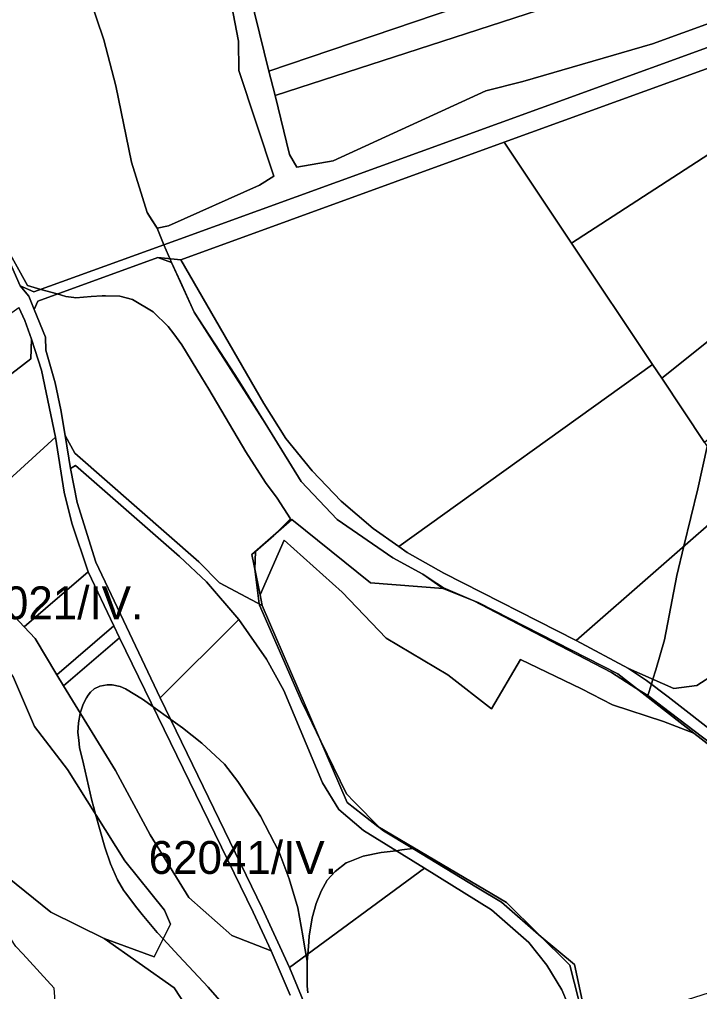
# Model space of a CAD drawing. Extents: x -521939 to -516426, y -1197857 to -1189551.
# Drawn here: x -518736 to -518425.7, y -1194982.1 to -1194538.7 of the extents above; entities that cross this region are included whole.
import ezdxf

# ---------------------------------------------------------------- set-up
doc = ezdxf.new("R2010")
doc.units = 0
for name, color, linetype in [('95560013', 7, 'Continuous'), ('95610013', 7, 'Continuous'), ('95620013', 7, 'Continuous'), ('95640013', 7, 'Continuous'), ('95660013', 7, 'Continuous')]:
    doc.layers.add(name, color=color, linetype=linetype)

msp = doc.modelspace()

# ---------------------------------------------------------------- linework, layer by layer
at = {"layer": '95560013'}
for points in [[(-518410.36, -1194442.61), (-518392.22, -1194484.25), (-518451.13, -1194504.23), (-518622.14, -1194562.23), (-518632.98, -1194518.19), (-518460.61, -1194459.67)], [(-518622.14, -1194562.23), (-518451.13, -1194504.23), (-518392.22, -1194484.25), (-518386.35, -1194497.79), (-518450.38, -1194518.57), (-518619.36, -1194573.41)], [(-518373.59, -1194527.14), (-518419.54, -1194539.87), (-518447.07, -1194549.8), (-518506.27, -1194566.99), (-518523.18, -1194571.3), (-518592.86, -1194603.17), (-518609.4, -1194606.14), (-518612.69, -1194600.31), (-518619.36, -1194573.41), (-518450.38, -1194518.57), (-518386.35, -1194497.79)], [(-518367.68, -1194539.54), (-518356.28, -1194557.82), (-518484.07, -1194640.7), (-518514.78, -1194594.72), (-518386.51, -1194548.14)], [(-518447.08, -1194696.09), (-518484.07, -1194640.7), (-518356.28, -1194557.82), (-518340.99, -1194583.11), (-518325.54, -1194608.45), (-518442.87, -1194702.39)], [(-518562.92, -1194779.16), (-518574.64, -1194770.93), (-518589.15, -1194758.48), (-518602.39, -1194744.68), (-518614.37, -1194729.87), (-518624.47, -1194713.9), (-518662.28, -1194648.3), (-518514.78, -1194594.72), (-518484.07, -1194640.7), (-518447.08, -1194696.09)], [(-518423.4, -1194731.62), (-518442.87, -1194702.39), (-518325.54, -1194608.45), (-518307.55, -1194638.13)], [(-518730.4, -1194684.49), (-518730.79, -1194693.56), (-518777.63, -1194729.6), (-518855.5, -1194789.32), (-518865.86, -1194763.22), (-518860.9, -1194759.36), (-518736.23, -1194670.16), (-518733.51, -1194676.1)], [(-518481.99, -1194821.99), (-518542.37, -1194791.36), (-518559, -1194781.92), (-518562.92, -1194779.16), (-518447.08, -1194696.09), (-518442.87, -1194702.39), (-518423.4, -1194731.62), (-518412.48, -1194747.98), (-518406.89, -1194756.35)], [(-518481.99, -1194821.99), (-518406.89, -1194756.35), (-518395.85, -1194772.88), (-518376.44, -1194801.94), (-518410.77, -1194832.23), (-518426.93, -1194842.54), (-518437.35, -1194843.87), (-518458.12, -1194834.75)]]:
    msp.add_lwpolyline(points, close=True, dxfattribs=at)
at = {"layer": '95610013'}
msp.add_lwpolyline([(-518648.33, -1194484.39), (-518635.96, -1194548.55), (-518635.85, -1194562), (-518619.89, -1194610.13), (-518626.4, -1194614.29), (-518667.97, -1194632.81), (-518673.12, -1194633.99), (-518677.75, -1194626.77), (-518684.82, -1194603.84), (-518691.92, -1194568.93), (-518697.48, -1194547.94), (-518710.33, -1194509.64)], dxfattribs=at)
for points in [[(-518667.07, -1194951.45), (-518674.42, -1194966.29), (-518697.27, -1194957.86), (-518721.6, -1194945.89), (-518745.52, -1194926.78), (-518800.02, -1194866.93), (-518820.29, -1194839.32), (-518835.53, -1194820.44), (-518765.72, -1194771.38), (-518719.57, -1194729.28), (-518715.58, -1194754.38), (-518712.02, -1194768.46), (-518704.64, -1194790.68), (-518733.74, -1194815.77), (-518749.9, -1194798.59), (-518761.09, -1194783.03), (-518767.51, -1194780.53), (-518770.85, -1194784.96), (-518750.08, -1194821.88), (-518738.64, -1194838.92), (-518729.05, -1194861.24), (-518713.96, -1194880.83), (-518687.89, -1194922.47), (-518669.78, -1194944.97)], [(-518635.94, -1194812.42), (-518671.75, -1194848.16), (-518701.05, -1194786.3), (-518709.67, -1194758.99), (-518712.72, -1194743.47), (-518710.37, -1194742.17), (-518662.98, -1194783.62), (-518650.66, -1194795.28)], [(-518692.91, -1194815.24), (-518718.88, -1194837.59), (-518728.73, -1194821.13), (-518733.74, -1194815.77), (-518704.64, -1194790.68)], [(-518551.19, -1194925.86), (-518612.73, -1194971.22), (-518625.28, -1194944.03), (-518671.75, -1194848.16), (-518635.94, -1194812.42), (-518623.29, -1194830.57), (-518615.31, -1194844.82), (-518597.64, -1194886.99), (-518590.23, -1194899.11), (-518578.98, -1194908.61)], [(-518690.24, -1194820.82), (-518715.84, -1194842.65), (-518718.88, -1194837.59), (-518692.91, -1194815.24)], [(-518690.24, -1194820.82), (-518629.33, -1194945.99), (-518621.14, -1194963.55), (-518639.03, -1194956.62), (-518658.6, -1194939.28), (-518676.38, -1194910.65), (-518692.19, -1194881.36), (-518715.84, -1194842.65)], [(-518612.73, -1194971.22), (-518551.19, -1194925.86), (-518520.66, -1194944.85), (-518503.52, -1194959.79), (-518495.28, -1194970.1), (-518488.5, -1194981.42), (-518483.3, -1194993.56), (-518479.79, -1195006.28), (-518583.67, -1195045.33), (-518599.24, -1195003.9)]]:
    msp.add_lwpolyline(points, close=True, dxfattribs=at)
at = {"layer": '95620013'}
for points in [[(-518442.17, -1194859), (-518465.35, -1194851.3), (-518479.49, -1194844.01), (-518507.34, -1194830.62), (-518520.62, -1194853.23), (-518540.54, -1194837.64), (-518568.59, -1194820.97), (-518588.67, -1194800), (-518615.19, -1194776.18), (-518626.13, -1194801.22), (-518629.87, -1194782.81), (-518611.71, -1194766.87), (-518575.86, -1194795.7), (-518542.69, -1194798.26), (-518526.37, -1194804.79), (-518463.01, -1194837.27), (-518428.24, -1194864.28)], [(-518477.04, -1195000.54), (-518484.79, -1194970.06), (-518513.79, -1194941.58), (-518572.38, -1194906.86), (-518586.43, -1194895.87), (-518625.17, -1194805.96), (-518626.13, -1194801.22), (-518615.19, -1194776.18), (-518588.67, -1194800), (-518568.59, -1194820.97), (-518540.54, -1194837.64), (-518520.62, -1194853.23), (-518507.34, -1194830.62), (-518479.49, -1194844.01), (-518465.35, -1194851.3), (-518442.17, -1194859), (-518428.24, -1194864.28), (-518400.82, -1194885.57), (-518302.06, -1194944.78)]]:
    msp.add_lwpolyline(points, close=True, dxfattribs=at)
at = {"layer": '95640013'}
for points in [[(-518719.92, -1194464.77), (-518710.33, -1194509.64), (-518697.48, -1194547.94), (-518691.92, -1194568.93), (-518684.82, -1194603.84), (-518677.75, -1194626.77), (-518673.12, -1194633.99), (-518670.02, -1194641.47), (-518729.32, -1194662.99), (-518735.68, -1194660.28), (-518749.75, -1194628.33), (-518778.85, -1194562.27), (-518784.67, -1194547.47), (-518789.28, -1194532.25), (-518792.66, -1194516.7), (-518794.77, -1194500.94), (-518795.17, -1194469.16), (-518789.82, -1194390.1), (-518787.62, -1194357.85), (-518785.49, -1194356.68), (-518774.24, -1194362.95), (-518768.4, -1194363.91), (-518713.15, -1194395.12), (-518719.42, -1194447.81)], [(-518625.17, -1194805.96), (-518644.64, -1194795.63), (-518654.08, -1194786.18), (-518710.66, -1194736.6), (-518715.14, -1194728.52), (-518717.06, -1194716.71), (-518719.62, -1194704.53), (-518723.86, -1194689.63), (-518724.12, -1194683.6), (-518729.2, -1194670.98), (-518727.55, -1194667.14), (-518672.89, -1194647.3), (-518666.51, -1194649.62), (-518656.27, -1194672.17), (-518623.89, -1194722.86), (-518607.41, -1194749.43), (-518591.06, -1194766.84), (-518565.58, -1194784.24), (-518551.9, -1194791.69), (-518542.69, -1194798.26), (-518575.86, -1194795.7), (-518611.71, -1194766.87), (-518629.87, -1194782.81), (-518626.13, -1194801.22)], [(-518719.57, -1194729.28), (-518765.72, -1194771.38), (-518766.88, -1194766.36), (-518770.01, -1194755.88), (-518773.9, -1194742.58), (-518777.63, -1194729.6), (-518730.79, -1194693.56), (-518730.4, -1194684.49), (-518725.91, -1194698.62)], [(-518458.12, -1194834.75), (-518437.35, -1194843.87), (-518426.93, -1194842.54), (-518410.77, -1194832.23), (-518376.44, -1194801.94), (-518335.14, -1194763.37), (-518297.28, -1194730.31), (-518275.98, -1194713.4), (-518265.96, -1194706.53), (-518259.19, -1194717.76), (-518284.47, -1194739.67), (-518413.12, -1194851.17), (-518415.72, -1194854.89), (-518417.07, -1194860.7), (-518416.02, -1194866.37), (-518440.03, -1194847.7), (-518449.87, -1194840.31)]]:
    msp.add_lwpolyline(points, close=True, dxfattribs=at)
for points in [[(-518398.68, -1194543), (-518498.27, -1194579.14), (-518664.63, -1194639.51), (-518670.02, -1194641.47), (-518673.12, -1194633.99), (-518667.97, -1194632.81), (-518626.4, -1194614.29), (-518619.89, -1194610.13), (-518635.85, -1194562), (-518635.96, -1194548.55), (-518648.33, -1194484.39), (-518643.9, -1194474.45), (-518632.98, -1194518.19), (-518622.14, -1194562.23), (-518619.36, -1194573.41), (-518612.69, -1194600.31), (-518609.4, -1194606.14), (-518592.86, -1194603.17), (-518523.18, -1194571.3), (-518506.27, -1194566.99), (-518447.07, -1194549.8), (-518419.54, -1194539.87)], [(-518386.51, -1194548.14), (-518514.78, -1194594.72), (-518662.28, -1194648.3), (-518672.89, -1194647.3), (-518727.55, -1194667.14), (-518729.2, -1194670.98), (-518731.66, -1194664.89), (-518735.68, -1194660.28), (-518729.32, -1194662.99), (-518670.02, -1194641.47), (-518664.63, -1194639.51), (-518498.27, -1194579.14), (-518398.68, -1194543)], [(-518749.75, -1194628.33), (-518735.68, -1194660.28), (-518731.66, -1194664.89), (-518729.2, -1194670.98), (-518724.12, -1194683.6), (-518723.86, -1194689.63), (-518719.62, -1194704.53), (-518717.06, -1194716.71), (-518715.14, -1194728.52), (-518712.72, -1194743.47), (-518709.67, -1194758.99), (-518701.05, -1194786.3), (-518671.75, -1194848.16), (-518625.28, -1194944.03), (-518612.73, -1194971.22), (-518599.24, -1195003.9)], [(-518400.82, -1194885.57), (-518428.24, -1194864.28), (-518463.01, -1194837.27), (-518526.37, -1194804.79), (-518542.69, -1194798.26), (-518551.9, -1194791.69), (-518565.58, -1194784.24), (-518591.06, -1194766.84), (-518607.41, -1194749.43), (-518623.89, -1194722.86), (-518656.27, -1194672.17), (-518666.51, -1194649.62), (-518672.89, -1194647.3), (-518662.28, -1194648.3), (-518624.47, -1194713.9), (-518614.37, -1194729.87), (-518602.39, -1194744.68), (-518589.15, -1194758.48), (-518574.64, -1194770.93), (-518562.92, -1194779.16), (-518559, -1194781.92), (-518542.37, -1194791.36), (-518481.99, -1194821.99), (-518458.12, -1194834.75), (-518449.87, -1194840.31), (-518440.03, -1194847.7), (-518416.02, -1194866.37)], [(-518612.46, -1194983.75), (-518621.14, -1194963.55), (-518629.33, -1194945.99), (-518690.24, -1194820.82), (-518692.91, -1194815.24), (-518704.64, -1194790.68), (-518712.02, -1194768.46), (-518715.58, -1194754.38), (-518719.57, -1194729.28), (-518725.91, -1194698.62), (-518730.4, -1194684.49), (-518733.51, -1194676.1), (-518736.23, -1194670.16)], [(-518483.3, -1194993.56), (-518488.5, -1194981.42), (-518495.28, -1194970.1), (-518503.52, -1194959.79), (-518520.66, -1194944.85), (-518551.19, -1194925.86), (-518578.98, -1194908.61), (-518590.23, -1194899.11), (-518597.64, -1194886.99), (-518615.31, -1194844.82), (-518623.29, -1194830.57), (-518635.94, -1194812.42), (-518650.66, -1194795.28), (-518662.98, -1194783.62), (-518710.37, -1194742.17), (-518712.72, -1194743.47), (-518715.14, -1194728.52), (-518710.66, -1194736.6), (-518654.08, -1194786.18), (-518644.64, -1194795.63), (-518625.17, -1194805.96), (-518586.43, -1194895.87), (-518572.38, -1194906.86), (-518513.79, -1194941.58), (-518484.79, -1194970.06), (-518477.04, -1195000.54)], [(-518749.9, -1194798.59), (-518733.74, -1194815.77), (-518728.73, -1194821.13), (-518718.88, -1194837.59), (-518715.84, -1194842.65), (-518692.19, -1194881.36), (-518676.38, -1194910.65), (-518658.6, -1194939.28), (-518639.03, -1194956.62), (-518621.14, -1194963.55), (-518612.46, -1194983.75)], [(-518718.38, -1195002.82), (-518720.07, -1194980.61), (-518734.46, -1194964.98), (-518737.6, -1194961.57), (-518744.12, -1194951.55), (-518757.12, -1194929), (-518770.47, -1194902.08), (-518776.75, -1194901.38), (-518809.32, -1194874.65), (-518820.69, -1194854.64), (-518850.19, -1194802.69), (-518843.34, -1194811.13), (-518835.53, -1194820.44), (-518820.29, -1194839.32), (-518800.02, -1194866.93), (-518745.52, -1194926.78), (-518721.6, -1194945.89), (-518697.27, -1194957.86), (-518665.42, -1194980.49), (-518648.26, -1195006.39)], [(-518648.26, -1195006.39), (-518665.42, -1194980.49), (-518697.27, -1194957.86), (-518674.42, -1194966.29), (-518667.07, -1194951.45), (-518669.78, -1194944.97), (-518687.89, -1194922.47), (-518713.96, -1194880.83), (-518729.05, -1194861.24), (-518738.64, -1194838.92)]]:
    msp.add_lwpolyline(points, dxfattribs=at)
at = {"layer": '95660013'}
for points in [[(-518710.33, -1194509.64), (-518697.48, -1194547.94), (-518691.92, -1194568.93), (-518684.82, -1194603.84), (-518677.75, -1194626.77), (-518675.69, -1194629.98), (-518673.12, -1194633.99), (-518670.02, -1194641.47), (-518667.98, -1194646.39), (-518667.33, -1194647.82), (-518666.51, -1194649.62), (-518662.54, -1194658.37), (-518656.27, -1194672.17), (-518637.62, -1194700.71), (-518634.02, -1194706.51), (-518623.89, -1194722.86), (-518607.41, -1194749.43), (-518591.06, -1194766.84), (-518565.58, -1194784.24), (-518551.9, -1194791.69), (-518548.61, -1194794.07), (-518542.56, -1194797.98), (-518528.62, -1194803.89), (-518505.03, -1194816.28), (-518465.84, -1194836.61), (-518454.69, -1194843.73), (-518449.25, -1194847.09), (-518448.12, -1194847.96), (-518442.75, -1194852.05), (-518416.67, -1194871.87)], [(-518422.14, -1194733.51), (-518426.46, -1194752.87), (-518432.79, -1194778.99), (-518436.02, -1194792.3), (-518441.62, -1194821.69), (-518445.59, -1194835.45), (-518446.92, -1194839.67), (-518447.65, -1194841.97), (-518449.25, -1194847.09), (-518454.69, -1194843.73), (-518465.84, -1194836.61), (-518505.03, -1194816.28), (-518528.62, -1194803.89), (-518542.56, -1194797.98), (-518548.61, -1194794.07), (-518551.9, -1194791.69), (-518565.58, -1194784.24), (-518591.06, -1194766.84), (-518607.41, -1194749.43), (-518623.89, -1194722.86), (-518634.02, -1194706.51), (-518637.62, -1194700.71), (-518656.27, -1194672.17), (-518662.54, -1194658.37), (-518666.51, -1194649.62), (-518667.33, -1194647.82), (-518667.98, -1194646.39), (-518670.02, -1194641.47), (-518673.12, -1194633.99), (-518675.69, -1194629.98), (-518677.75, -1194626.77), (-518684.82, -1194603.84), (-518691.92, -1194568.93), (-518697.48, -1194547.94), (-518710.33, -1194509.64)], [(-518479.17, -1194986.02), (-518482.78, -1194969.81), (-518497.93, -1194957.15), (-518497.98, -1194957.1), (-518516.09, -1194941.34), (-518526.97, -1194934.75), (-518556.43, -1194916.92), (-518569.9, -1194908.77), (-518571.18, -1194907.76), (-518572.16, -1194906.99), (-518571.64, -1194907.3), (-518583.26, -1194895.6), (-518586.82, -1194892.01), (-518598.47, -1194867.92), (-518606.54, -1194851.24), (-518606.58, -1194851.16), (-518606.62, -1194851.06), (-518626.46, -1194805.85), (-518626.54, -1194805.23), (-518628.53, -1194789.42), (-518628.22, -1194781.36), (-518619.92, -1194774.08), (-518613.72, -1194767.88), (-518612.34, -1194766.5), (-518618.31, -1194757.13), (-518623.65, -1194749.88), (-518632.71, -1194735.98), (-518649.62, -1194707.32), (-518652.88, -1194701.92), (-518661.88, -1194687.08), (-518665.56, -1194682.1), (-518668.07, -1194678.7), (-518675.02, -1194672.04), (-518684.33, -1194666.52), (-518690.09, -1194664.96), (-518696.72, -1194664.76), (-518698.28, -1194664.71), (-518703.18, -1194665.12), (-518710.17, -1194665.71), (-518711.13, -1194665.57), (-518714.8, -1194665.04), (-518718.73, -1194663.94), (-518726.18, -1194661.85), (-518732.31, -1194660.13), (-518743.19, -1194640.3)], [(-518743.19, -1194640.3), (-518732.31, -1194660.13), (-518726.18, -1194661.85), (-518718.73, -1194663.94), (-518714.8, -1194665.04), (-518711.13, -1194665.57), (-518710.17, -1194665.71), (-518703.18, -1194665.12), (-518698.28, -1194664.71), (-518696.72, -1194664.76), (-518690.09, -1194664.96), (-518684.33, -1194666.52), (-518675.02, -1194672.04), (-518668.07, -1194678.7), (-518665.56, -1194682.1), (-518661.88, -1194687.08), (-518652.88, -1194701.92), (-518649.62, -1194707.32), (-518632.71, -1194735.98), (-518623.65, -1194749.88), (-518618.31, -1194757.13), (-518612.34, -1194766.5), (-518613.72, -1194767.88), (-518619.92, -1194774.08), (-518628.22, -1194781.36), (-518628.53, -1194789.42), (-518626.54, -1194805.23), (-518626.46, -1194805.85), (-518606.62, -1194851.06), (-518606.58, -1194851.16), (-518606.54, -1194851.24), (-518598.47, -1194867.92), (-518586.82, -1194892.01), (-518583.26, -1194895.6), (-518571.64, -1194907.3), (-518572.16, -1194906.99), (-518571.18, -1194907.76), (-518569.9, -1194908.77), (-518556.43, -1194916.92), (-518561.46, -1194917.55), (-518564.05, -1194917.88), (-518565.39, -1194918.05), (-518570.86, -1194918.73), (-518579.14, -1194920.31), (-518585.23, -1194922.8), (-518586.84, -1194923.46), (-518591.86, -1194927.31), (-518595.59, -1194931.39), (-518598.27, -1194936.29), (-518600.6, -1194942), (-518602.47, -1194948.54), (-518603.75, -1194956.93), (-518604.14, -1194961.65), (-518604.42, -1194965.1), (-518604.69, -1194968.36), (-518605.16, -1194965.64), (-518606.03, -1194960.55), (-518606.68, -1194956.72), (-518608.88, -1194943.87), (-518612.97, -1194930.69), (-518617.52, -1194918.56), (-518626.03, -1194902.11), (-518631.34, -1194893.91), (-518636.3, -1194886.25), (-518642.36, -1194878.44), (-518652.74, -1194868.87), (-518661.61, -1194861.9), (-518666.96, -1194858.03), (-518674.93, -1194852.28), (-518679.86, -1194848.72), (-518687.5, -1194844), (-518690.07, -1194842.95), (-518693.62, -1194842.25), (-518695.9, -1194842.25), (-518699.28, -1194842.89), (-518701.91, -1194844), (-518703.6, -1194845.51), (-518704.56, -1194846.91), (-518705.4, -1194848.14), (-518706.92, -1194851.05), (-518708.24, -1194855.08), (-518708.32, -1194855.31), (-518709.08, -1194859.51), (-518709.25, -1194863.94), (-518708.87, -1194867.4), (-518708.5, -1194870.77), (-518706.69, -1194878.29), (-518702.95, -1194894.97), (-518702.19, -1194897.71), (-518701.23, -1194901.16), (-518697.06, -1194916.2), (-518694.44, -1194923.84), (-518691.29, -1194931.24), (-518688.41, -1194935.86), (-518687.62, -1194937.13), (-518682.43, -1194943.9), (-518679.92, -1194946.96), (-518673.15, -1194955.21), (-518670.39, -1194958.16), (-518663.24, -1194965.83), (-518649.83, -1194980.06), (-518643.64, -1194987.35)], [(-518416.67, -1194871.87), (-518442.75, -1194852.05), (-518448.12, -1194847.96), (-518449.25, -1194847.09), (-518447.65, -1194841.97), (-518446.92, -1194839.67), (-518445.59, -1194835.45), (-518441.62, -1194821.69), (-518436.02, -1194792.3), (-518432.79, -1194778.99), (-518426.46, -1194752.87), (-518422.14, -1194733.51)], [(-518643.64, -1194987.35), (-518649.83, -1194980.06), (-518663.24, -1194965.83), (-518670.39, -1194958.16), (-518673.15, -1194955.21), (-518679.92, -1194946.96), (-518682.43, -1194943.9), (-518687.62, -1194937.13), (-518688.41, -1194935.86), (-518691.29, -1194931.24), (-518694.44, -1194923.84), (-518697.06, -1194916.2), (-518701.23, -1194901.16), (-518702.19, -1194897.71), (-518702.95, -1194894.97), (-518706.69, -1194878.29), (-518708.5, -1194870.77), (-518708.87, -1194867.4), (-518709.25, -1194863.94), (-518709.08, -1194859.51), (-518708.32, -1194855.31), (-518708.24, -1194855.08), (-518706.92, -1194851.05), (-518705.4, -1194848.14), (-518704.56, -1194846.91), (-518703.6, -1194845.51), (-518701.91, -1194844), (-518699.28, -1194842.89), (-518695.9, -1194842.25), (-518693.62, -1194842.25), (-518690.07, -1194842.95), (-518687.5, -1194844), (-518679.86, -1194848.72), (-518674.93, -1194852.28), (-518666.96, -1194858.03), (-518661.61, -1194861.9), (-518652.74, -1194868.87), (-518642.36, -1194878.44), (-518636.3, -1194886.25), (-518631.34, -1194893.91), (-518626.03, -1194902.11), (-518617.52, -1194918.56), (-518612.97, -1194930.69), (-518608.88, -1194943.87), (-518606.68, -1194956.72), (-518606.03, -1194960.55), (-518605.16, -1194965.64), (-518604.69, -1194968.36), (-518604.69, -1194979.45), (-518604.36, -1194982.73)], [(-518604.36, -1194982.73), (-518604.69, -1194979.45), (-518604.69, -1194968.36), (-518604.42, -1194965.1), (-518604.14, -1194961.65), (-518603.75, -1194956.93), (-518602.47, -1194948.54), (-518600.6, -1194942), (-518598.27, -1194936.29), (-518595.59, -1194931.39), (-518591.86, -1194927.31), (-518586.84, -1194923.46), (-518585.23, -1194922.8), (-518579.14, -1194920.31), (-518570.86, -1194918.73), (-518565.39, -1194918.05), (-518564.05, -1194917.88), (-518561.46, -1194917.55), (-518556.43, -1194916.92), (-518526.97, -1194934.75), (-518516.09, -1194941.34), (-518497.98, -1194957.1), (-518497.93, -1194957.15), (-518482.78, -1194969.81), (-518479.17, -1194986.02)], [(-518718.38, -1195002.82), (-518720.07, -1194980.61), (-518734.46, -1194964.98), (-518737.6, -1194961.57)]]:
    msp.add_lwpolyline(points, dxfattribs=at)

# ---------------------------------------------------------------- texts
for s, p in [('62021/IV.', (-518765.36, -1194812.33)), ('62041/IV.', (-518677.01, -1194928.47))]:
    msp.add_text(s, height=15, rotation=0, dxfattribs=at).set_placement(p)

doc.saveas('drawing.dxf')
